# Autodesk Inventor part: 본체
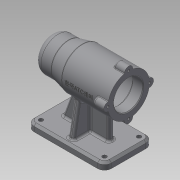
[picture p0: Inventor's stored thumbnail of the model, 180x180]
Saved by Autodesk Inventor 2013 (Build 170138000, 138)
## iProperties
Created: 2019-07
Part Number: 본체
Material: 일반
Document SubType Name: Modeling
Designer: Administrator
Density: 1 g/cm^3
Author: Administrator
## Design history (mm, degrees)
sketch "스케치1"
  geometry: L1 (0, 0)-(-112, 0); L2 (-112, 0)-(-112, 25); L3 (-112, 25)-(-87, 25); L4 (-87, 25)-(-67, 30); L5 (-67, 30)-(0, 30); L6 (0, 30)-(0, 21); L7 (0, 21)-(-15, 21); L8 (-15, 21)-(-15, 24); L9 (-15, 24)-(-69, 24); L10 (-69, 24)-(-69, 21); L11 (-69, 21)-(-81, 21); L12 (-81, 21)-(-81, 17.5); L13 (-81, 17.5)-(-99, 17.5); L14 (-99, 17.5)-(-99, 16); L15 (-99, 16)-(-103, 16); L16 (-103, 16)-(-103, 10.5); L17 (-103, 10.5)-(-106, 10.5); L18 (-106, 10.5)-(-106, 0); L19 (-112, 0)-(-106, 0); 1 further point
  constraints: 38 end point, 10 horizontal, 8 vertical, 1 midpoint, 1 point on line, 1 vertical alignment
  dimensions: "d0" = 112 distance of L1.start L1.end; "d1" = 21 diameter of L17 L1; "d2" = 32 diameter of L15 L1; "d3" = 35 diameter of L13 L1; "d4" = 42 diameter of L11 L1; "d5" = 42 diameter of L7 L1; "d6" = 48 diameter of L9 L1; "d7" = 50 diameter of L3 L1; "d8" = 60 diameter of L5 L1; "d9" = 25 distance of L2.end L3.end; "d10" = 45 horizontal distance of L2.end L4.end; "d11" = 15 distance of L6.end L7.end; "d12" = 54 distance of L8.end L9.end; "d13" = 12 distance of L10.end L11.end; "d14" = 18 distance of L12.end L13.end; "d15" = 4 distance of L14.end L15.end; "d16" = 3 distance of L16.end L17.end
revolve "회전1" sketch "스케치1" stored, may be unused: angle "d17" = 90 deg
sketch "스케치2"
  geometry: L1 (0, 0)-(0, 30); C1 r 30 at (0, 0) reference; C2 r 6 at (0, 30); 1 further point
  constraints: 2 coincident, 2 end point, 1 centre point, 1 vertical
  dimensions: "d18" = 30 distance of L1.start L1.end; "d19" = 12 diameter of C2
extrude "돌출1" join sketch "스케치2" distance "d20" = 16; taper "d21" = 0 deg
hole "구멍1" sketch "스케치2" diameter "d22" = 3.242; stored, may be unused: countersink angle "d26" = 90 deg, drill point angle "d28" = 118 deg; dims "d23" = 8, "d24" = 4, "d25" = 2, "d27" = 11
fillet "모깎기2" dims "d30" = 3
fillet "모깎기3" dims "d31" = 1
chamfer "모따기1" distance "d35" = 1; stored, may be unused: second distance "d36" = 2, angle "d37" = 45 deg
sketch "스케치3"
  geometry: L1 (-112, -70)-(0, -70); L2 (0, -70)-(0, -80); L3 (0, -80)-(-112, -80); L4 (-112, -80)-(-112, -70); 2 further points
  constraints: 8 end point, 2 parallel, 1 horizontal, 1 midpoint, 1 perpendicular, 1 vertical alignment
  dimensions: "d38" = 80 distance from line of L3 point (0, 0); "d39" = 10 distance of L1.end L2.end; "d40" = 112 distance of L1.start L1.end
extrude "돌출2" join sketch "스케치3" stored distance "d41" = 70; taper "d42" = 0 deg
fillet "모깎기4" dims "d43" = 10
sketch "스케치4"
  geometry: L1 (-10, -10)-(-10, -60) reference; L2 (102, -60)-(102, -10) reference; L3 (10, -31)-(77, -31); L4 (77, -31)-(77, -39); L5 (77, -39)-(10, -39); L6 (10, -39)-(10, -31); 3 further points
  constraints: 8 end point, 2 midpoint, 2 parallel, 1 horizontal, 1 horizontal alignment, 1 perpendicular
  dimensions: "d44" = 8 distance of L3.end L4.end; "d47" = 25 distance between parallel lines of L2 L4; "d48" = 20 distance between parallel lines of L1 L6
extrude "돌출3" join sketch "스케치4" stored distance "d49" = 70; taper "d50" = 0 deg
feature "면 기울기1" dims angle "d51" = 20 deg
node "작업 평면1"
sketch "스케치5"
  geometry: L1 (-80, 35)-(-70, 35) reference; L2 (-70, 28)-(-36.792, 22.144); L3 (-70, -25)-(-70, 25) reference; L4 (-70, 35)-(-70, 25) reference; 1 further point
  constraints: 2 end point, 1 point on line
  dimensions: "d54" = 7 distance of L2.start L1.end; "d56" = 100 deg angle of L2 L3
feature "리브1" sketch "스케치5" dims "d57" = 1, "d58" = 8, "d59" = 0, "d60" = 0, "d61" = 1, "d62" = 1
sketch "스케치6"
  geometry: A1 r 10 centre (92, 10) between (92, 0) and (102, 10) reference; A2 r 10 centre (92, 60) between (102, 60) and (92, 70) reference; A3 r 10 centre (0, 60) between (0, 70) and (-10, 60) reference; A4 r 10 centre (0, 10) between (-10, 10) and (0, 0) reference; 5 further points
  constraints: 4 coincident
hole "구멍2" sketch "스케치6" at (0, 60), (0, 10), (92, 10), (92, 60) diameter "d66" = 6; stored, may be unused: countersink angle "d70" = 90 deg, drill point angle "d72" = 118 deg; dims "d67" = 6, "d68" = 4, "d69" = 2, "d71" = 8
fillet "모깎기13" dims "d78" = 3
fillet "모깎기14" dims "d79" = 3
fillet "모깎기15" dims "d80" = 3, "d81" = 0.3
node "작업 평면2"
sketch "스케치7"
  geometry: 2 further points
  constraints: 1 horizontal alignment, 1 other
  dimensions: "d83" = 42 distance of point (0, 0) point (-42, 0)
feature "엠보싱1" sketch "스케치7" dims "d0" = 112, "d1" = 21, "d2" = 32, "d3" = 35, "d4" = 42, "d5" = 42, "d6" = 48, "d7" = 50, "d8" = 60, "d9" = 25, "d10" = 45, "d11" = 15, "d12" = 54, "d13" = 12, "d14" = 18, "d15" = 4, "d16" = 3, "d84" = 0.5, "d85" = 0
chamfer "모따기2" distance "d86" = 3; stored, may be unused: second distance "d87" = 2, angle "d88" = 45 deg
node "솔리드1"
pattern_circular "원형 패턴1" dims "d33" = 360 deg
mirror "대칭1"
other parameters: "d52" = -56
